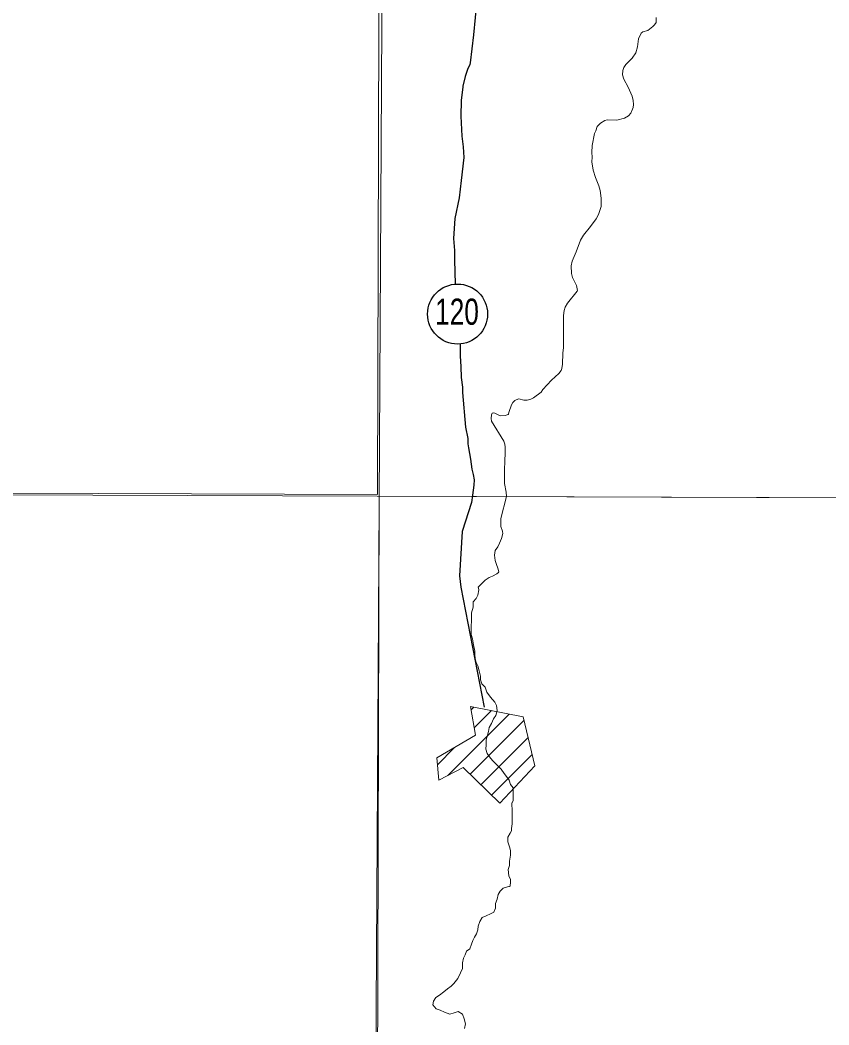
# Model space of a CAD drawing. Extents: x 553962 to 842807, y 8883888 to 9032388.
# Drawn here: x 606613 to 608778, y 8908475 to 8911165 of the extents above; entities that cross this region are included whole.
import ezdxf
from ezdxf.enums import TextEntityAlignment as Align

# ---------------------------------------------------------------- set-up
doc = ezdxf.new("R2010")
doc.units = 0
doc.header["$LTSCALE"] = 200
doc.layers.add('6', color=7, linetype='Continuous', lineweight=13)

msp = doc.modelspace()

# ---------------------------------------------------------------- linework, layer by layer
at = {"layer": '6'}
for p, q in [((574653.9, 8910009.3), (626625.7, 8909822.1)), ((607820.8, 8909318.7), (607828.1, 8909326)), ((607758.6, 8909143.3), (607922.8, 8909307.5)), ((607828.8, 8909270.1), (607875.4, 8909316.8)), ((607817.9, 8909146.1), (607962.5, 8909290.7)), ((607846.6, 8909118.2), (607973.3, 8909244.9)), ((607730.5, 8909171.9), (607776.5, 8909217.8)), ((607875.3, 8909090.3), (607984.2, 8909199.2))]:
    msp.add_line(p, q, dxfattribs=at)
for points in [[(607657.7, 8924743.3), (607574.2, 8909874.9), (607492.3, 8896026.7)], [(608315.5, 8911171.7), (608315.6, 8911158.5), (608311.6, 8911151.9), (608307.3, 8911147.5), (608293.6, 8911136.9), (608280, 8911133), (608275.9, 8911129.4), (608268.8, 8911114.5), (608265.9, 8911093.2), (608261.9, 8911077.1), (608251.5, 8911062.7), (608234.4, 8911045.7), (608229.6, 8911037.8), (608226.7, 8911030.1), (608226, 8911018.3), (608229.5, 8911006.7), (608241.4, 8910985), (608251.6, 8910961.2), (608254.2, 8910949.4), (608255.3, 8910939.2), (608254.1, 8910930.4), (608252.7, 8910925.9), (608247.8, 8910915.8), (608242.3, 8910908.2), (608231, 8910902.2), (608210.4, 8910897.2), (608184.7, 8910897.9), (608178.9, 8910895.7), (608167, 8910888.8), (608158.1, 8910879.6), (608154.4, 8910868.3), (608151.1, 8910860.9), (608144.3, 8910828.8), (608143.3, 8910810.6), (608144.4, 8910798), (608143.9, 8910785.4), (608147.5, 8910763.3), (608153.7, 8910743.5), (608162.5, 8910721.4), (608166.3, 8910708.8), (608168.7, 8910688.2), (608168.3, 8910666.1), (608161.6, 8910644.7), (608155.1, 8910632.9), (608140.4, 8910611.9), (608121.6, 8910588.8), (608113.6, 8910576.1), (608102.1, 8910544.4), (608090.7, 8910519.2), (608088.7, 8910506.7), (608089.2, 8910486.1), (608091.9, 8910475.9), (608103.1, 8910454.4), (608105.7, 8910441.4), (608104.8, 8910439.1), (608078.6, 8910407.5), (608072, 8910396.6)], [(608072, 8910396.6), (608069.6, 8910387.1), (608068.1, 8910373.8), (608068.3, 8910308.2), (608067.6, 8910288.4), (608066.2, 8910273.5), (608065.1, 8910243.4), (608063.5, 8910232.3), (608061.9, 8910227), (608055.7, 8910219), (608035.7, 8910200.6), (608012.5, 8910176.3), (608007.7, 8910168.6), (607987.3, 8910153.6), (607980.8, 8910149.9), (607970.7, 8910147.2), (607961.9, 8910147.3), (607948.5, 8910151.3), (607941.1, 8910148.7), (607937.3, 8910146.5), (607932.1, 8910141.4), (607928.5, 8910134.9), (607921.3, 8910114.9), (607920.8, 8910110.1), (607919.9, 8910108.9), (607911.6, 8910106.4), (607900.5, 8910105.6), (607894.4, 8910107.2), (607884.3, 8910112.4), (607879.3, 8910113.2), (607877.1, 8910112.3), (607875.3, 8910108.4), (607873.8, 8910098.7), (607875, 8910091.5), (607907.8, 8910037.4), (607910.9, 8910030.1), (607911.9, 8910021.7)], [(607911.9, 8910021.7), (607911.9, 8910002.7), (607911.9, 8910002.7), (607910.6, 8909987.8), (607909.5, 8909957.7), (607910.2, 8909924.6), (607914.4, 8909900.9), (607915.5, 8909889.9), (607900.2, 8909830.5)], [(607900.2, 8909830.5), (607900.1, 8909819.3), (607900, 8909809.1), (607905, 8909796.9), (607905.6, 8909789.5)], [(607905.8, 8909790.3), (607901.8, 8909777.5), (607896.7, 8909764.3), (607892.5, 8909755.2), (607884.8, 8909745.4), (607883.4, 8909732.4), (607884.8, 8909718.5), (607888.1, 8909707.3), (607892.1, 8909698.2), (607894.9, 8909687.9)], [(607894.5, 8909687.5), (607889, 8909682.9), (607877.7, 8909676.8), (607868.6, 8909672.8), (607858.3, 8909665.8), (607851.2, 8909658.7), (607839.5, 8909647.1)], [(607839.2, 8909647.8), (607841.5, 8909640), (607838.4, 8909625.7), (607834.3, 8909616.6), (607826.1, 8909607.5), (607826, 8909593.2), (607821.8, 8909578), (607821.6, 8909556.6), (607820.5, 8909542.3), (607820.5, 8909532.2), (607820.4, 8909519.9), (607824.3, 8909508.7), (607827.3, 8909492.4), (607830.2, 8909476.1), (607830.2, 8909465.9), (607831.1, 8909455.7), (607834.1, 8909445.5), (607838.1, 8909436.3), (607842.1, 8909423), (607846, 8909408.8), (607846, 8909398.6), (607849, 8909388.4), (607858, 8909379.2), (607863, 8909365.9), (607872.1, 8909352.6), (607884.2, 8909339.3), (607888.2, 8909330.1), (607890.2, 8909316.8), (607887, 8909303.6), (607880.8, 8909294.5), (607874.7, 8909282.3), (607868.5, 8909271.1), (607867.4, 8909260.9), (607864.3, 8909250.8), (607861.1, 8909238.6), (607861.1, 8909225.3), (607859.9, 8909213.1), (607863.9, 8909201.9), (607870, 8909192.7), (607878.1, 8909183.5), (607885.1, 8909176.3), (607893.2, 8909168.1), (607901.3, 8909159.9), (607909.3, 8909148.7), (607915.4, 8909140.5)], [(607915.4, 8909140.5), (607922.4, 8909130.2), (607926.4, 8909119), (607933.5, 8909109.8), (607933.4, 8909097.6), (607933.3, 8909086.4), (607933.2, 8909075.2), (607929.2, 8909068.9)], [(607928.5, 8908994.8), (607924.7, 8908988.9), (607918.5, 8908977.7), (607918.4, 8908965.5), (607923.4, 8908952.2), (607926.4, 8908942), (607926.3, 8908929.8), (607923.2, 8908913.5), (607923.1, 8908902.3), (607920, 8908891.2), (607921.9, 8908874.8), (607925.9, 8908864.6), (607925.8, 8908854.4), (607923.9, 8908845.1)], [(607924.2, 8908846.6), (607906.4, 8908841.3), (607898.2, 8908833.2), (607893, 8908824.1), (607889.9, 8908811.9), (607885.8, 8908800.7), (607885.7, 8908787.5), (607881.5, 8908777.3), (607872.3, 8908772.3), (607861.1, 8908767.2), (607849.9, 8908763.2), (607843.7, 8908752.1), (607839.6, 8908739.9), (607838.5, 8908729.7), (607835.3, 8908719.5), (607829.2, 8908710.4), (607825.1, 8908701.3), (607821.9, 8908691.1), (607816.8, 8908678.9), (607808.6, 8908672.9), (607804.4, 8908662.7), (607800.3, 8908653.6), (607797.2, 8908641.3), (607797.1, 8908626.1), (607791.9, 8908614.9), (607784.7, 8908599.7), (607774.4, 8908586.5), (607767.2, 8908579.4), (607757, 8908572.3), (607747.8, 8908564.2), (607735.5, 8908555.2), (607726.3, 8908549.1), (607720.2, 8908539), (607718.1, 8908528.8), (607727.2, 8908518.6), (607737.3, 8908514.4), (607749.5, 8908509.2), (607763.7, 8908504.1), (607774.9, 8908508.1), (607786.1, 8908511.1), (607797.2, 8908503.9), (607802.2, 8908491.6), (607805.2, 8908478.3), (607803.1, 8908466.1)]]:
    msp.add_lwpolyline(points, dxfattribs=at)
for points in [[(607600.8, 8920952.4), (596639.8, 8920989.8), (596608.8, 8909934.4), (607569.8, 8909894.9)], [(618535.2, 8909853.3), (607574.3, 8909890.7), (607543.3, 8898835.3), (618504.2, 8898795.8)], [(607819.3, 8909327.7), (607832, 8909250.5), (607728.8, 8909189.8), (607734.5, 8909130.7), (607798.9, 8909164.5), (607897.1, 8909069.2), (607991.4, 8909168.6), (607960.2, 8909300.2)]]:
    msp.add_lwpolyline(points, close=True, dxfattribs=at)
at = {"layer": '6', "lineweight": 25}
for points in [[(607784.9, 8911999.6), (607782.1, 8911967.5), (607781.3, 8911929.5), (607788, 8911886.9), (607792.5, 8911839.5), (607788.3, 8911760.4), (607788.9, 8911720.9), (607793.1, 8911695.9), (607802, 8911666.8), (607810.5, 8911630.6), (607820.1, 8911605.6), (607832.4, 8911579), (607837.3, 8911566.1), (607839.5, 8911553.2), (607843.7, 8911515.3), (607845.8, 8911475.8), (607845.1, 8911393), (607845.4, 8911323.6), (607839.9, 8911277.2), (607839.1, 8911261.7), (607839.2, 8911246.2), (607835.7, 8911217.9), (607827.2, 8911125.4)], [(607827.2, 8911125.4), (607818.3, 8911050.1), (607817.3, 8911045.7), (607811.1, 8911032.1), (607804.2, 8911013.7), (607798.7, 8910987.7)], [(607798.7, 8910987.7), (607798.4, 8910986.3), (607793.6, 8910949.1), (607793.1, 8910907.6), (607795.5, 8910854.2), (607799.3, 8910825.8), (607801.4, 8910796.7), (607794, 8910735.7)], [(607794, 8910735.7), (607788.4, 8910689.2), (607776.8, 8910633.3), (607773.3, 8910579.9), (607775.9, 8910548.2), (607775.9, 8910522), (607777.9, 8910458.8)], [(607790.9, 8910298.5), (607791.2, 8910292), (607790.9, 8910265.3), (607792.9, 8910237.8), (607794, 8910207.8), (607797.2, 8910181.9), (607797.8, 8910168.2), (607805.9, 8910075.3), (607811.7, 8910045.2), (607812, 8910030.6), (607813.2, 8910020.3), (607819.2, 8909989.3), (607822.2, 8909962.7), (607826.4, 8909948.1), (607828.6, 8909934.3), (607828.1, 8909919.8), (607824.7, 8909893.1), (607821.4, 8909873.3)], [(607821.4, 8909873.3), (607797, 8909796.1), (607789.4, 8909676.9), (607793.4, 8909647.3), (607855.8, 8909325.6)]]:
    msp.add_lwpolyline(points, dxfattribs=at)
msp.add_circle((607784.4, 8910378), 80.3, dxfattribs=at)
at = {"layer": '6'}
msp.add_spline([(607929.6, 8909069.6), (607930.5, 8909038.8), (607930.5, 8909019.9), (607928.3, 8908994.5)], degree=3, dxfattribs=at)

# ---------------------------------------------------------------- texts
at = {"layer": '6', "width": 0.75}
msp.add_text('120', height=70, dxfattribs=at).set_placement((607782.8, 8910349.3), align=Align.CENTER)

doc.saveas('drawing.dxf')
